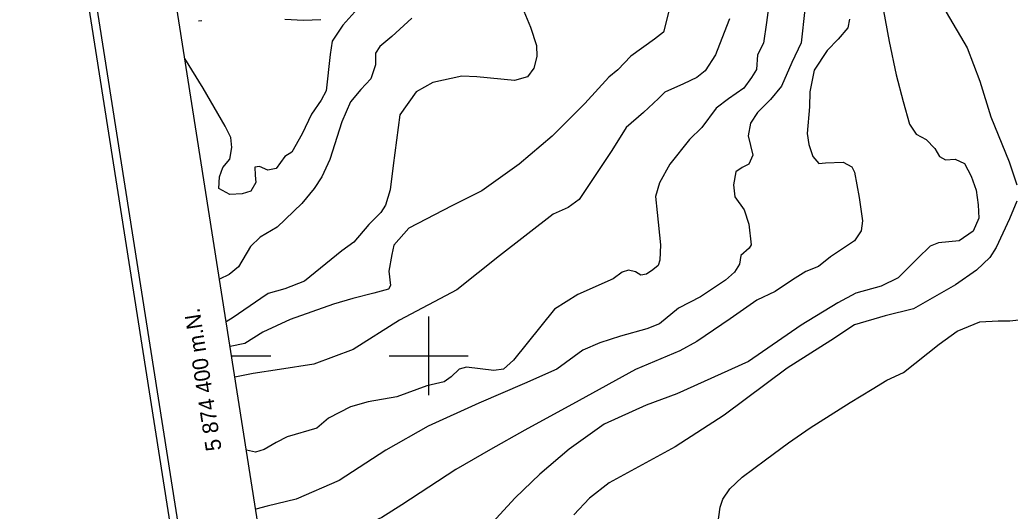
# Model space of a CAD drawing. Extents: x 643342 to 646936, y 5873857 to 5876103.
# Drawn here: x 643496.2 to 643747.6, y 5874360.6 to 5874485.2 of the extents above; entities that cross this region are included whole.
import ezdxf

# ---------------------------------------------------------------- set-up
doc = ezdxf.new("R2010")
doc.units = 0
for name, color, linetype in [('Niveau 1', 7, 'Continuous'), ('Niveau 2', 7, 'Continuous'), ('Niveau 3', 7, 'Continuous'), ('Niveau 60', 7, 'Continuous'), ('Niveau 61', 7, 'Continuous')]:
    doc.layers.add(name, color=color, linetype=linetype)

msp = doc.modelspace()

# ---------------------------------------------------------------- linework, layer by layer
at = {"layer": 'Niveau 1'}
for points in [[(643686.66, 5874491.65), (643685.76, 5874484.52), (643684.93, 5874479.31), (643683.43, 5874476.3), (643683.17, 5874472.57), (643681.94, 5874470.55), (643679.95, 5874467.85), (643676.06, 5874465.21), (643672.99, 5874462.77), (643669.31, 5874457.89), (643666.17, 5874454.84), (643661.2, 5874448.64), (643658.57, 5874443.87), (643657.59, 5874440.44), (643657.96, 5874436.31), (643658.81, 5874428.18), (643658.69, 5874424.25), (643658.23, 5874422.89), (643656.91, 5874421.82), (643655.25, 5874420.7), (643653.87, 5874420.45), (643652.5, 5874421.27)], [(643581.27, 5874487.22), (643578.19, 5874483.84), (643575.52, 5874479.79), (643575.02, 5874476.42), (643574, 5874467.19), (643572.71, 5874464.81), (643570.23, 5874461.25), (643567.89, 5874456.29), (643565.28, 5874451.66), (643563.51, 5874450.54), (643561.34, 5874447.49), (643559.16, 5874447.04), (643557.08, 5874448.03), (643555.93, 5874447.8), (643556, 5874445.79), (643556.18, 5874443.92), (643554.86, 5874441.78), (643552.7, 5874441.1), (643549.56, 5874440.91), (643546.73, 5874442.41)], [(643563.52, 5874485.4), (643568.23, 5874485.14), (643572.66, 5874485.33)], [(643546.73, 5874442.41), (643546.91, 5874445.39), (643547.75, 5874447.72), (643549.53, 5874449.9), (643550.08, 5874452.8), (643549.83, 5874455.38), (643548.39, 5874458.21), (643542.8, 5874467.86), (643538.13, 5874475.42)], [(643652.5, 5874421.27), (643650.7, 5874421.69), (643649.1, 5874421.18), (643646.78, 5874419.53), (643637.85, 5874415.57), (643631.97, 5874411.8), (643621.51, 5874398.91), (643619.02, 5874396.65), (643616.58, 5874396.29), (643609.57, 5874397.16), (643607.74, 5874396.62), (643605.69, 5874394.65), (643603.92, 5874393.41), (643599.55, 5874392.39), (643591.93, 5874389.63), (643584.64, 5874388.33), (643580.18, 5874387.07), (643574.57, 5874384.15), (643571.63, 5874381.61), (643564.07, 5874379.46), (643561.27, 5874378), (643558.26, 5874376.28), (643556.09, 5874375.6), (643553.81, 5874376.09), (643553.74, 5874376.14)], [(643656.43, 5874343.15), (643663.37, 5874347.4), (643671.08, 5874352.19), (643672.19, 5874353.02), (643673.08, 5874354.89), (643674.01, 5874361.65), (643674.66, 5874363.62), (643676.43, 5874366.3), (643679.59, 5874369.23), (643685.46, 5874373.62), (643691.34, 5874377.89), (643696.79, 5874381.76), (643706.97, 5874388.12), (643712.58, 5874391.52), (643716.28, 5874393.79), (643720.48, 5874395.75), (643729.53, 5874402.96), (643734.09, 5874406.27), (643739.9, 5874408.63), (643744.49, 5874408.83), (643747.44, 5874408.88), (643750.49, 5874409.17)]]:
    msp.add_lwpolyline(points, dxfattribs=at)
at = {"layer": 'Niveau 2'}
for points in [[(643721.28, 5874507.49), (643723.14, 5874502.5), (643727.3, 5874495.57), (643731.34, 5874487.19), (643736.63, 5874478.1), (643739.85, 5874469.65), (643742.65, 5874460.57), (643747.3, 5874449.17), (643749.22, 5874443.37)], [(643622.85, 5874490.53), (643625.85, 5874483.32), (643627.33, 5874478.71), (643627.47, 5874475.87), (643626.68, 5874472.94), (643625.12, 5874470.77), (643621.8, 5874469.86), (643612.22, 5874470.72), (643608.45, 5874470.95), (643601.09, 5874469.29), (643596.85, 5874466.98), (643592.7, 5874461.12), (643590.96, 5874448.24), (643590.24, 5874442.12), (643589.08, 5874438.21), (643587.84, 5874436.32), (643584.84, 5874433.3), (643581.04, 5874428.78), (643577.97, 5874426.59), (643568.49, 5874418.92), (643563.51, 5874417.02), (643559.29, 5874415.78), (643557.41, 5874414.53), (643550.37, 5874409.71), (643548.63, 5874408.63)], [(643714.81, 5874490.77), (643716.84, 5874479.7), (643718.65, 5874471.24), (643720.42, 5874464.47), (643721.99, 5874458.76), (643723.75, 5874456.18), (643726.22, 5874454.86), (643728.43, 5874452.56), (643729.67, 5874450.53), (643731.15, 5874449.72), (643733.62, 5874449.84), (643735.96, 5874448.75), (643737.65, 5874445.56), (643738.91, 5874441.98), (643739.46, 5874438.33), (643739.64, 5874434.89), (643738.15, 5874431.64), (643734.6, 5874429.15), (643729.34, 5874428.64)], [(643595.76, 5874485.61), (643590.68, 5874480.96), (643587.64, 5874478.41), (643586.5, 5874476.76), (643586.54, 5874473.79), (643585.35, 5874470.24), (643582.79, 5874467.5), (643580.15, 5874464.4), (643577.93, 5874459.32), (643574.95, 5874449.78), (643572.9, 5874445.43), (643570.95, 5874442.4), (643567.79, 5874438.66), (643561.57, 5874432.61), (643557.24, 5874430.06), (643554.77, 5874427.69), (643551.74, 5874422.55), (643549.35, 5874420.66), (643546.94, 5874419.42)], [(643660.99, 5874487.37), (643659.58, 5874482.11), (643657.28, 5874480.34), (643651.33, 5874475.96), (643648, 5874472.55), (643645.71, 5874470.66), (643639.62, 5874464.01), (643631.33, 5874455.72), (643622.95, 5874448.61), (643613.47, 5874441.88), (643605.84, 5874438.05), (643594.98, 5874432.37), (643591.15, 5874428.09), (643590.67, 5874425.67), (643589.89, 5874421.44), (643590.35, 5874417.81), (643589.84, 5874416.93), (643586.07, 5874415.85), (643580.8, 5874414.51), (643575.89, 5874413.09), (643564.87, 5874409.18), (643557.89, 5874406.01), (643553.36, 5874403.09), (643549.67, 5874402.37), (643549.62, 5874402.36)], [(643676.36, 5874485.48), (643675.59, 5874483.49), (643672.82, 5874476.32), (643670.13, 5874472.24), (643668.05, 5874470.61), (643664.67, 5874468.98), (643659.92, 5874466.85), (643658.3, 5874465.27), (643654.51, 5874461.69), (643650.15, 5874457.94), (643646.45, 5874452.1), (643638.18, 5874439.65), (643635.43, 5874437.6), (643631.59, 5874435.92), (643617.99, 5874425.34), (643607.16, 5874416.7), (643592.6, 5874409), (643580.84, 5874401.57), (643570.85, 5874397.87), (643562.17, 5874396.56), (643555.45, 5874395.55), (643550.84, 5874394.61)], [(643695.47, 5874487.84), (643694.57, 5874479.39), (643692.18, 5874474.38), (643689.53, 5874468.39), (643686.77, 5874465.02), (643683.41, 5874461.71), (643681.65, 5874459.04), (643681.11, 5874455.76), (643682.26, 5874450.86), (643681.28, 5874448.62), (643679.59, 5874447.74), (643677.92, 5874446.63), (643677.39, 5874443.36), (643677.67, 5874440.28), (643680.07, 5874437.06), (643681.23, 5874433.36), (643681.81, 5874428.18), (643681.3, 5874427.29), (643679.23, 5874425.43), (643678.84, 5874423.25)], [(643706.79, 5874485.41), (643706.39, 5874483.21), (643703.93, 5874480.34), (643701.12, 5874477.44), (643697.79, 5874472.45), (643696.74, 5874466.97), (643696.61, 5874463.13), (643696.02, 5874456.38), (643696.51, 5874453.56), (643697.48, 5874450.55), (643699.05, 5874448.79), (643700.69, 5874448.95), (643705.15, 5874449.14), (643707.38, 5874447.92), (643708.09, 5874446.56), (643709.25, 5874440.11), (643710.12, 5874434.23), (643709.76, 5874431.69), (643708.1, 5874429.14), (643701.98, 5874425.09), (643698.89, 5874422.65), (643695.71, 5874421.39), (643692.36, 5874419.28), (643687.91, 5874416.35), (643683.28, 5874414.11)], [(643749.22, 5874439.18), (643747.37, 5874434.7), (643743.99, 5874427.44), (643742.44, 5874424.9), (643739.05, 5874421.71), (643733.72, 5874417.97), (643723.03, 5874411.92), (643715.87, 5874410.15), (643708.05, 5874407.84), (643702.02, 5874403.91), (643690.96, 5874396.88), (643675.03, 5874384.96), (643662.53, 5874376.95), (643645.77, 5874367.82), (643640.82, 5874363.88), (643636.83, 5874359.68)], [(643729.34, 5874428.64), (643727.29, 5874427.84), (643724.13, 5874424.79), (643719.15, 5874419.78), (643714.86, 5874417.69), (643708.41, 5874415.88), (643703.8, 5874413.4), (643694.52, 5874407.74), (643681.19, 5874398.58), (643662.94, 5874390.38), (643655.18, 5874387.48), (643644.54, 5874382.64), (643635.68, 5874376.3), (643628.24, 5874369.99), (643621.95, 5874364.02), (643615.21, 5874356.59)], [(643678.84, 5874423.25), (643677.61, 5874421.22), (643675.32, 5874419.22), (643669, 5874414.92), (643663.37, 5874412.11), (643658.55, 5874408.08), (643655.37, 5874406.82), (643648.72, 5874404.99), (643643.46, 5874403.29), (643639.16, 5874401.45), (643632.53, 5874396.64), (643624.28, 5874392.99), (643612.74, 5874387.95), (643599.86, 5874382.19), (643589.13, 5874376.04), (643577.26, 5874368.36), (643566.4, 5874363.63), (643559.04, 5874361.84), (643556.11, 5874361.08)], [(643683.28, 5874414.11), (643676.52, 5874409.41), (643668.09, 5874403.59), (643663.71, 5874401.26), (643652.48, 5874396.49), (643638.23, 5874388.68), (643624.43, 5874381.16), (643615.69, 5874376.27), (643606.86, 5874371.13), (643593.2, 5874362.2), (643588.08, 5874358.97), (643580.96, 5874355.78), (643569.79, 5874351.73), (643563.45, 5874345.3), (643561.17, 5874343.17), (643559.11, 5874342.03)]]:
    msp.add_lwpolyline(points, dxfattribs=at)
at = {"layer": 'Niveau 3'}
msp.add_line((643541.62, 5874484.91), (643542.41, 5874485.03), dxfattribs=at)
at = {"layer": 'Niveau 60'}
msp.add_line((643549.99, 5874400), (643559.99, 5874400), dxfattribs=at)
for points in [[(643342.09, 5875579.85), (646664.86, 5876102.57), (646935.9, 5874379.74), (643613.15, 5873856.99), (643342.1, 5875579.83)], [(643342.09, 5875579.85), (646664.86, 5876102.57), (646935.9, 5874379.74), (643613.15, 5873856.99), (643342.1, 5875579.83)], [(643342.09, 5875579.85), (646664.86, 5876102.57), (646935.9, 5874379.74), (643613.15, 5873856.99), (643342.1, 5875579.83)], [(643344.38, 5875578.18), (646663.19, 5876100.29), (646933.6, 5874381.38), (643614.81, 5873859.28), (643344.38, 5875578.18)], [(643344.38, 5875578.18), (646663.19, 5876100.29), (646933.6, 5874381.38), (643614.81, 5873859.28), (643344.38, 5875578.18)], [(643344.38, 5875578.18), (646663.19, 5876100.29), (646933.6, 5874381.38), (643614.81, 5873859.28), (643344.38, 5875578.18)]]:
    msp.add_lwpolyline(points, dxfattribs=at)
msp.add_lwpolyline([(643367.26, 5875561.52), (646133.22, 5875996.67), (646397.42, 5874317.29), (643631.46, 5873882.15)], close=True, dxfattribs=at)
at = {"layer": 'Niveau 61'}
for points in [[(643600, 5874410), (643600, 5874400), (643600, 5874390)], [(643590, 5874400), (643600, 5874400), (643610, 5874400)]]:
    msp.add_lwpolyline(points, dxfattribs=at)

# ---------------------------------------------------------------- texts
msp.add_text('5 874 400 m.N.', height=4, rotation=98.9405, dxfattribs=at).set_placement((643547.49, 5874376.19))

doc.saveas('drawing.dxf')
